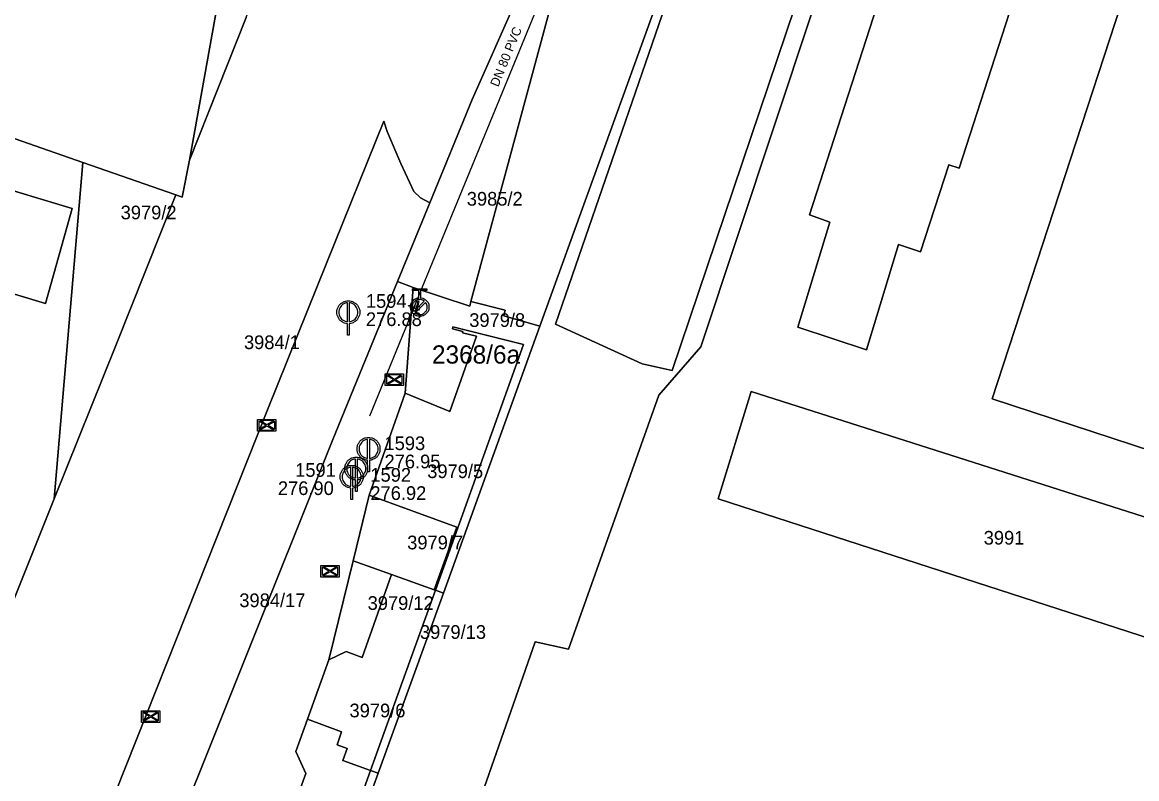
# Model space of a CAD drawing. Extents: x -570104 to -569328, y -1087857 to -1087418.
# Drawn here: x -569780.6 to -569658.3, y -1087753.5 to -1087670.5 of the extents above; entities that cross this region are included whole.
import ezdxf

# ---------------------------------------------------------------- set-up
doc = ezdxf.new("R2010")
doc.units = 0
for name, color, linetype in [('Adresní místo-text', 7, 'Continuous'), ('Armatura vodovodní', 7, 'Continuous'), ('Default', 7, 'Continuous'), ('Dešťová vpusť', 7, 'Continuous'), ('Hydrant', 7, 'Continuous'), ('Kanalizační šachta', 7, 'Continuous'), ('Parcela-polygon', 7, 'Continuous'), ('Parcela-text', 7, 'Continuous'), ('Popis šachty', 7, 'Continuous'), ('Přípojka vodovodní popis', 7, 'Continuous'), ('Vodovodní přípojka', 7, 'Continuous')]:
    doc.layers.add(name, color=color, linetype=linetype)

msp = doc.modelspace()

# ---------------------------------------------------------------- linework, layer by layer
at = {"layer": 'Armatura vodovodní'}
for points in [[(-569737.06, -1087701.1), (-569737.32, -1087702.32), (-569737.39, -1087702.3), (-569737.14, -1087701.08), (-569737.06, -1087701.1)], [(-569737.03, -1087702.12), (-569738.18, -1087701.65), (-569738.15, -1087701.57), (-569737, -1087702.05), (-569737.03, -1087702.12)]]:
    msp.add_lwpolyline(points, dxfattribs=at)
at = {"layer": 'Default'}
for points in [[(-569744.89, -1087703.59), (-569745.15, -1087703.57), (-569745.41, -1087703.42), (-569745.71, -1087703.26), (-569745.88, -1087702.96), (-569746.04, -1087702.66), (-569746.04, -1087702.34), (-569746.04, -1087702.01), (-569745.87, -1087701.71), (-569745.7, -1087701.41), (-569745.41, -1087701.25), (-569745.11, -1087701.09), (-569744.79, -1087701.09), (-569744.48, -1087701.09), (-569744.18, -1087701.25), (-569743.88, -1087701.41), (-569743.71, -1087701.71), (-569743.54, -1087702.01), (-569743.54, -1087702.34), (-569743.54, -1087702.66), (-569743.7, -1087702.96), (-569743.87, -1087703.26), (-569744.17, -1087703.42), (-569744.43, -1087703.57), (-569744.69, -1087703.59)], [(-569744.89, -1087701.3), (-569745.09, -1087701.32), (-569745.31, -1087701.43), (-569745.55, -1087701.57), (-569745.69, -1087701.82), (-569745.83, -1087702.07), (-569745.83, -1087702.34), (-569745.83, -1087702.61), (-569745.7, -1087702.86), (-569745.56, -1087703.1), (-569745.31, -1087703.24), (-569745.1, -1087703.36), (-569744.89, -1087703.38)], [(-569744.69, -1087703.38), (-569744.48, -1087703.36), (-569744.27, -1087703.24), (-569744.02, -1087703.1), (-569743.88, -1087702.86), (-569743.75, -1087702.61), (-569743.75, -1087702.34), (-569743.75, -1087702.07), (-569743.89, -1087701.82), (-569744.03, -1087701.57), (-569744.28, -1087701.43), (-569744.49, -1087701.32), (-569744.69, -1087701.3)], [(-569736.86, -1087700.76), (-569736.5, -1087700.79), (-569736.25, -1087701.05), (-569735.95, -1087701.34), (-569735.95, -1087701.76), (-569735.95, -1087702.17), (-569736.25, -1087702.47), (-569736.54, -1087702.76), (-569736.96, -1087702.76), (-569737.37, -1087702.76), (-569737.66, -1087702.47), (-569737.95, -1087702.17), (-569737.95, -1087701.76), (-569737.95, -1087701.34), (-569737.66, -1087701.05), (-569737.41, -1087700.79), (-569737.05, -1087700.76)], [(-569736.45, -1087701.12), (-569736.67, -1087700.94), (-569736.96, -1087700.94), (-569737.29, -1087700.94), (-569737.53, -1087701.18), (-569737.77, -1087701.42), (-569737.77, -1087701.76), (-569737.77, -1087702.05), (-569737.59, -1087702.26)], [(-569737.46, -1087702.4), (-569737.25, -1087702.57), (-569736.96, -1087702.57), (-569736.62, -1087702.57), (-569736.38, -1087702.33), (-569736.14, -1087702.09), (-569736.14, -1087701.76), (-569736.14, -1087701.47), (-569736.32, -1087701.25)], [(-569742.67, -1087718.58), (-569742.93, -1087718.56), (-569743.19, -1087718.41), (-569743.49, -1087718.25), (-569743.66, -1087717.95), (-569743.82, -1087717.65), (-569743.82, -1087717.33), (-569743.82, -1087717), (-569743.65, -1087716.7), (-569743.48, -1087716.4), (-569743.19, -1087716.24), (-569742.89, -1087716.08), (-569742.57, -1087716.08), (-569742.26, -1087716.08), (-569741.96, -1087716.24), (-569741.66, -1087716.4), (-569741.49, -1087716.7), (-569741.32, -1087717), (-569741.32, -1087717.33), (-569741.32, -1087717.65), (-569741.48, -1087717.95), (-569741.65, -1087718.25), (-569741.95, -1087718.41), (-569742.21, -1087718.56), (-569742.47, -1087718.58)], [(-569742.67, -1087716.29), (-569742.87, -1087716.31), (-569743.09, -1087716.42), (-569743.33, -1087716.56), (-569743.47, -1087716.81), (-569743.61, -1087717.06), (-569743.61, -1087717.33), (-569743.61, -1087717.6), (-569743.48, -1087717.85), (-569743.34, -1087718.09), (-569743.09, -1087718.23), (-569742.88, -1087718.35), (-569742.67, -1087718.37)], [(-569742.47, -1087718.37), (-569742.26, -1087718.35), (-569742.05, -1087718.23), (-569741.8, -1087718.09), (-569741.66, -1087717.85), (-569741.53, -1087717.6), (-569741.53, -1087717.33), (-569741.53, -1087717.06), (-569741.67, -1087716.81), (-569741.81, -1087716.56), (-569742.06, -1087716.42), (-569742.27, -1087716.31), (-569742.47, -1087716.29)], [(-569744.02, -1087720.74), (-569744.28, -1087720.72), (-569744.54, -1087720.57), (-569744.84, -1087720.41), (-569745.01, -1087720.11), (-569745.17, -1087719.81), (-569745.17, -1087719.49), (-569745.17, -1087719.16), (-569745, -1087718.86), (-569744.83, -1087718.56), (-569744.54, -1087718.4), (-569744.24, -1087718.24), (-569743.92, -1087718.24), (-569743.61, -1087718.24), (-569743.31, -1087718.4), (-569743.01, -1087718.56), (-569742.84, -1087718.86), (-569742.67, -1087719.16), (-569742.67, -1087719.49), (-569742.67, -1087719.81), (-569742.83, -1087720.11), (-569743, -1087720.41), (-569743.3, -1087720.57), (-569743.56, -1087720.72), (-569743.82, -1087720.74)], [(-569744.02, -1087718.45), (-569744.22, -1087718.47), (-569744.44, -1087718.58), (-569744.68, -1087718.72), (-569744.82, -1087718.97), (-569744.96, -1087719.22), (-569744.96, -1087719.49), (-569744.96, -1087719.76), (-569744.83, -1087720.01), (-569744.69, -1087720.25), (-569744.44, -1087720.39), (-569744.23, -1087720.51), (-569744.02, -1087720.53)], [(-569743.82, -1087720.53), (-569743.61, -1087720.51), (-569743.4, -1087720.39), (-569743.15, -1087720.25), (-569743.01, -1087720.01), (-569742.88, -1087719.76), (-569742.88, -1087719.49), (-569742.88, -1087719.22), (-569743.02, -1087718.97), (-569743.16, -1087718.72), (-569743.41, -1087718.58), (-569743.62, -1087718.47), (-569743.82, -1087718.45)], [(-569744.52, -1087721.64), (-569744.78, -1087721.62), (-569745.04, -1087721.47), (-569745.34, -1087721.31), (-569745.51, -1087721.01), (-569745.67, -1087720.71), (-569745.67, -1087720.39), (-569745.67, -1087720.06), (-569745.5, -1087719.76), (-569745.33, -1087719.46), (-569745.04, -1087719.3), (-569744.74, -1087719.14), (-569744.42, -1087719.14), (-569744.11, -1087719.14), (-569743.81, -1087719.3), (-569743.51, -1087719.46), (-569743.34, -1087719.76), (-569743.17, -1087720.06), (-569743.17, -1087720.39), (-569743.17, -1087720.71), (-569743.33, -1087721.01), (-569743.5, -1087721.31), (-569743.8, -1087721.47), (-569744.06, -1087721.62), (-569744.32, -1087721.64)], [(-569744.52, -1087719.35), (-569744.72, -1087719.37), (-569744.94, -1087719.48), (-569745.18, -1087719.62), (-569745.32, -1087719.87), (-569745.46, -1087720.12), (-569745.46, -1087720.39), (-569745.46, -1087720.66), (-569745.33, -1087720.91), (-569745.19, -1087721.15), (-569744.94, -1087721.29), (-569744.73, -1087721.41), (-569744.52, -1087721.43)], [(-569744.32, -1087721.43), (-569744.11, -1087721.41), (-569743.9, -1087721.29), (-569743.65, -1087721.15), (-569743.51, -1087720.91), (-569743.38, -1087720.66), (-569743.38, -1087720.39), (-569743.38, -1087720.12), (-569743.52, -1087719.87), (-569743.66, -1087719.62), (-569743.91, -1087719.48), (-569744.12, -1087719.37), (-569744.32, -1087719.35)]]:
    msp.add_open_spline(points, degree=3, dxfattribs=at)
at = {"layer": 'Dešťová vpusť'}
for points in [[(-569740.74, -1087710.38), (-569740.74, -1087709.1), (-569738.74, -1087709.1), (-569738.74, -1087710.38), (-569740.74, -1087710.38)], [(-569739.85, -1087709.73), (-569740.61, -1087709.28), (-569740.61, -1087710.19), (-569739.85, -1087709.73)], [(-569739.72, -1087709.81), (-569740.49, -1087710.26), (-569738.96, -1087710.26), (-569739.72, -1087709.81)], [(-569739.72, -1087709.66), (-569738.98, -1087709.22), (-569740.47, -1087709.22), (-569739.72, -1087709.66)], [(-569738.87, -1087710.17), (-569738.87, -1087709.3), (-569739.6, -1087709.73), (-569738.87, -1087710.17)], [(-569754.74, -1087715.39), (-569754.74, -1087714.11), (-569752.74, -1087714.11), (-569752.74, -1087715.39), (-569754.74, -1087715.39)], [(-569753.85, -1087714.74), (-569754.61, -1087714.29), (-569754.61, -1087715.2), (-569753.85, -1087714.74)], [(-569753.72, -1087714.82), (-569754.49, -1087715.27), (-569752.96, -1087715.27), (-569753.72, -1087714.82)], [(-569753.72, -1087714.67), (-569752.98, -1087714.23), (-569754.47, -1087714.23), (-569753.72, -1087714.67)], [(-569752.87, -1087715.18), (-569752.87, -1087714.31), (-569753.6, -1087714.74), (-569752.87, -1087715.18)], [(-569747.8, -1087731.39), (-569747.8, -1087730.11), (-569745.8, -1087730.11), (-569745.8, -1087731.39), (-569747.8, -1087731.39)], [(-569746.91, -1087730.74), (-569747.67, -1087730.29), (-569747.67, -1087731.2), (-569746.91, -1087730.74)], [(-569746.78, -1087730.82), (-569747.55, -1087731.27), (-569746.02, -1087731.27), (-569746.78, -1087730.82)], [(-569746.78, -1087730.67), (-569746.04, -1087730.23), (-569747.53, -1087730.23), (-569746.78, -1087730.67)], [(-569745.93, -1087731.18), (-569745.93, -1087730.31), (-569746.66, -1087730.74), (-569745.93, -1087731.18)], [(-569767.48, -1087747.33), (-569767.48, -1087746.05), (-569765.48, -1087746.05), (-569765.48, -1087747.33), (-569767.48, -1087747.33)], [(-569766.59, -1087746.68), (-569767.35, -1087746.23), (-569767.35, -1087747.14), (-569766.59, -1087746.68)], [(-569766.46, -1087746.61), (-569765.72, -1087746.17), (-569767.21, -1087746.17), (-569766.46, -1087746.61)], [(-569765.61, -1087747.12), (-569765.61, -1087746.25), (-569766.34, -1087746.68), (-569765.61, -1087747.12)], [(-569766.46, -1087746.76), (-569767.23, -1087747.21), (-569765.7, -1087747.21), (-569766.46, -1087746.76)]]:
    msp.add_lwpolyline(points, dxfattribs=at)
at = {"layer": 'Hydrant'}
for points in [[(-569737.05, -1087700.76), (-569737.05, -1087699.95), (-569737.74, -1087699.95), (-569737.74, -1087699.76), (-569736.17, -1087699.76), (-569736.17, -1087699.95), (-569736.86, -1087699.95), (-569736.86, -1087700.76)], [(-569737.59, -1087702.26), (-569736.45, -1087701.12)], [(-569736.32, -1087701.25), (-569737.46, -1087702.4)]]:
    msp.add_lwpolyline(points, dxfattribs=at)
at = {"layer": 'Kanalizační šachta'}
for points in [[(-569744.89, -1087703.38), (-569744.89, -1087701.3)], [(-569744.69, -1087701.3), (-569744.69, -1087703.38)], [(-569744.69, -1087703.59), (-569744.69, -1087704.84), (-569744.89, -1087704.84), (-569744.89, -1087703.59)], [(-569742.67, -1087718.37), (-569742.67, -1087716.29)], [(-569742.47, -1087716.29), (-569742.47, -1087718.37)], [(-569744.02, -1087720.53), (-569744.02, -1087718.45)], [(-569743.82, -1087718.45), (-569743.82, -1087720.53)], [(-569742.47, -1087718.58), (-569742.47, -1087719.83), (-569742.67, -1087719.83), (-569742.67, -1087718.58)], [(-569744.52, -1087721.43), (-569744.52, -1087719.35)], [(-569744.32, -1087719.35), (-569744.32, -1087721.43)], [(-569743.82, -1087720.74), (-569743.82, -1087721.99), (-569744.02, -1087721.99), (-569744.02, -1087720.74)], [(-569744.32, -1087721.64), (-569744.32, -1087722.89), (-569744.52, -1087722.89), (-569744.52, -1087721.64)]]:
    msp.add_lwpolyline(points, dxfattribs=at)
at = {"layer": 'Parcela-polygon'}
for points in [[(-569793.31, -1087679.13), (-569773.93, -1087685.9), (-569763.73, -1087689.47), (-569763.01, -1087689.72), (-569762.21, -1087685.64), (-569752, -1087628.8), (-569745.23, -1087597.37), (-569762.2, -1087592.33), (-569767.95, -1087620.6), (-569765.97, -1087621.01), (-569768.78, -1087634.92), (-569770.77, -1087634.51), (-569772.66, -1087643.77), (-569791.42, -1087639.95)], [(-569746.61, -1087802.34), (-569724.3, -1087738.5), (-569720.63, -1087739.3), (-569710.72, -1087711.45), (-569706.1, -1087706.13), (-569677.75, -1087620.8), (-569675.24, -1087615.77), (-569677.5, -1087614.66), (-569709.27, -1087708.71), (-569712.54, -1087708.01), (-569722.07, -1087703.64), (-569688.74, -1087606.97), (-569723.77, -1087703.85), (-569734.36, -1087733.15), (-569741.51, -1087752.92), (-569751.5, -1087780.56), (-569757.72, -1087797.76)], [(-569656.08, -1087623.85), (-569670.86, -1087616.21), (-569676.9, -1087612.89), (-569676.97, -1087613.11), (-569677.5, -1087614.66), (-569675.24, -1087615.77), (-569677.75, -1087620.8), (-569706.1, -1087706.13), (-569710.72, -1087711.45), (-569720.63, -1087739.3), (-569724.3, -1087738.5), (-569746.61, -1087802.34)], [(-569673.39, -1087629.36), (-569668.72, -1087630.86), (-569668.3, -1087629.52), (-569666.4, -1087630.12), (-569666.82, -1087631.48), (-569661.77, -1087633.12), (-569664.35, -1087641.09), (-569663.2, -1087641.46), (-569677.76, -1087686.51), (-569678.9, -1087686.15), (-569681.99, -1087695.71), (-569684.42, -1087694.89), (-569687.94, -1087706.45), (-569695.48, -1087703.96), (-569691.97, -1087692.47), (-569694.18, -1087691.63), (-569674, -1087629.15), (-569673.39, -1087629.36)], [(-569674.15, -1087711.83), (-569651.41, -1087642.32), (-569633.25, -1087648.27), (-569643.94, -1087679.59), (-569636.12, -1087682.33), (-569634.05, -1087683.06), (-569635, -1087686.54), (-569636.91, -1087686.03), (-569640.33, -1087695.74), (-569648.38, -1087693.02), (-569656.5, -1087717.61), (-569674.15, -1087711.83)], [(-569773.64, -1087763.31), (-569753.65, -1087713.04), (-569747.16, -1087696.87), (-569740.88, -1087681.36), (-569740.52, -1087682.49), (-569739.04, -1087686.03), (-569737.61, -1087689.09), (-569736.88, -1087689.77), (-569735.85, -1087690.34), (-569731.2, -1087679), (-569716.23, -1087645.29)], [(-569756, -1087670), (-569762.21, -1087685.64), (-569763.01, -1087689.72), (-569763.73, -1087689.47), (-569770.3, -1087706), (-569777.06, -1087722.81), (-569788.63, -1087751.58)], [(-569818.35, -1087689.28), (-569815.37, -1087679.15), (-569816.77, -1087678.74), (-569815.83, -1087675.53), (-569812.15, -1087676.61), (-569813.02, -1087679.56), (-569775.08, -1087690.97), (-569778.02, -1087701.37), (-569801.13, -1087694.44), (-569802.83, -1087700.11), (-569820.04, -1087695.04), (-569818.35, -1087689.28)], [(-569788.63, -1087751.58), (-569777.06, -1087722.81), (-569773.93, -1087685.9), (-569793.31, -1087679.13)], [(-569776.13, -1087790.17), (-569766.4, -1087766), (-569746.5, -1087716.3), (-569739.39, -1087698.97), (-569735.85, -1087690.34), (-569736.88, -1087689.77), (-569737.61, -1087689.09), (-569739.04, -1087686.03), (-569740.52, -1087682.49), (-569740.88, -1087681.36), (-569747.16, -1087696.87), (-569753.65, -1087713.04), (-569773.64, -1087763.31), (-569779.09, -1087777.66), (-569780.06, -1087788.55)], [(-569768.4, -1087793.36), (-569751.5, -1087780.56), (-569741.51, -1087752.92), (-569742.34, -1087752.62), (-569749.29, -1087772), (-569755.49, -1087769.51), (-569749.45, -1087752.96), (-569750.55, -1087750.53), (-569749.27, -1087746.98), (-569746.92, -1087740.49), (-569744.26, -1087729.61), (-569742.5, -1087722.41), (-569738.57, -1087711.21), (-569737.69, -1087699.63), (-569739.39, -1087698.97), (-569746.5, -1087716.3), (-569766.4, -1087766), (-569776.13, -1087790.17)], [(-569704.22, -1087722.8), (-569700.58, -1087711.04), (-569643.25, -1087729.31), (-569646.89, -1087741.06), (-569647.63, -1087741.14), (-569704.22, -1087722.8)]]:
    msp.add_lwpolyline(points, dxfattribs=at)
for points in [[(-569734.91, -1087612.82), (-569741.25, -1087598.55), (-569745.23, -1087597.37), (-569752, -1087628.8), (-569762.21, -1087685.64), (-569756, -1087670)], [(-569691.3, -1087606.5), (-569700.1, -1087611.8), (-569705, -1087620), (-569716.23, -1087645.29), (-569731.33, -1087701.17), (-569727.59, -1087702.09), (-569727.74, -1087702.73), (-569723.77, -1087703.85), (-569688.74, -1087606.97)], [(-569688.74, -1087606.97), (-569722.07, -1087703.64), (-569712.54, -1087708.01), (-569709.27, -1087708.71), (-569677.5, -1087614.66), (-569676.97, -1087613.11), (-569676.9, -1087612.89), (-569677.4, -1087612.64)], [(-569673.39, -1087629.36), (-569674, -1087629.15), (-569694.18, -1087691.63), (-569691.97, -1087692.47), (-569695.48, -1087703.96), (-569687.94, -1087706.45), (-569684.42, -1087694.89), (-569681.99, -1087695.71), (-569678.9, -1087686.15), (-569677.76, -1087686.51), (-569663.2, -1087641.46), (-569664.35, -1087641.09), (-569661.77, -1087633.12), (-569666.82, -1087631.48), (-569666.4, -1087630.12), (-569668.3, -1087629.52), (-569668.72, -1087630.86)], [(-569674.15, -1087711.83), (-569656.5, -1087717.61), (-569648.38, -1087693.02), (-569640.33, -1087695.74), (-569636.91, -1087686.03), (-569635, -1087686.54), (-569634.05, -1087683.06), (-569636.12, -1087682.33), (-569643.94, -1087679.59), (-569633.25, -1087648.27), (-569651.41, -1087642.32)], [(-569735.85, -1087690.34), (-569739.39, -1087698.97), (-569737.69, -1087699.63), (-569731.47, -1087701.68), (-569731.33, -1087701.17), (-569716.23, -1087645.29), (-569731.2, -1087679)], [(-569816.77, -1087678.74), (-569815.37, -1087679.15), (-569818.35, -1087689.28), (-569820.04, -1087695.04), (-569802.83, -1087700.11), (-569801.13, -1087694.44), (-569778.02, -1087701.37), (-569775.08, -1087690.97), (-569813.02, -1087679.56), (-569812.15, -1087676.61), (-569815.83, -1087675.53)], [(-569777.06, -1087722.81), (-569770.3, -1087706), (-569763.73, -1087689.47), (-569773.93, -1087685.9)], [(-569733.31, -1087703.93), (-569725.57, -1087705.87), (-569735.24, -1087732.83), (-569734.36, -1087733.15), (-569723.77, -1087703.85), (-569727.74, -1087702.73), (-569727.59, -1087702.09), (-569731.33, -1087701.17), (-569731.47, -1087701.68), (-569737.69, -1087699.63), (-569738.57, -1087711.21), (-569733.66, -1087713.24), (-569730.71, -1087704.97), (-569732.26, -1087704.59), (-569732.22, -1087704.45), (-569733.37, -1087704.17)], [(-569733.37, -1087704.17), (-569732.22, -1087704.45), (-569732.26, -1087704.59), (-569730.71, -1087704.97), (-569733.66, -1087713.24), (-569738.57, -1087711.21), (-569742.5, -1087722.41), (-569732.9, -1087725.9), (-569735.36, -1087732.79), (-569735.24, -1087732.83), (-569725.57, -1087705.87), (-569733.31, -1087703.93)], [(-569704.22, -1087722.8), (-569647.63, -1087741.14), (-569646.89, -1087741.06), (-569643.25, -1087729.31), (-569700.58, -1087711.04)], [(-569732.9, -1087725.9), (-569742.5, -1087722.41), (-569744.26, -1087729.61), (-569740.04, -1087731.12), (-569735.36, -1087732.79)], [(-569740.04, -1087731.12), (-569744.26, -1087729.61), (-569746.92, -1087740.49), (-569745.01, -1087739.57), (-569743.28, -1087740.2)], [(-569742.34, -1087752.62), (-569738.5, -1087741.93), (-569735.24, -1087732.83), (-569735.36, -1087732.79), (-569740.04, -1087731.12), (-569743.28, -1087740.2), (-569745.01, -1087739.57), (-569746.92, -1087740.49), (-569749.27, -1087746.98), (-569745.52, -1087748.39), (-569746.03, -1087749.8), (-569744.9, -1087750.21), (-569745.38, -1087751.52)], [(-569741.51, -1087752.92), (-569734.36, -1087733.15), (-569735.24, -1087732.83), (-569738.5, -1087741.93), (-569742.34, -1087752.62)], [(-569749.27, -1087746.98), (-569750.55, -1087750.53), (-569749.45, -1087752.96), (-569755.49, -1087769.51), (-569749.29, -1087772), (-569742.34, -1087752.62), (-569745.38, -1087751.52), (-569744.9, -1087750.21), (-569746.03, -1087749.8), (-569745.52, -1087748.39)]]:
    msp.add_lwpolyline(points, close=True, dxfattribs=at)
at = {"layer": 'Vodovodní přípojka'}
for points in [[(-569704.52, -1087621.35), (-569704.61, -1087621.49), (-569737.51, -1087701.64), (-569737.59, -1087701.85), (-569742.47, -1087713.74)], [(-569737.51, -1087701.64), (-569737.5, -1087701.64), (-569737.23, -1087701.7), (-569736.95, -1087701.76)]]:
    msp.add_lwpolyline(points, dxfattribs=at)

# ---------------------------------------------------------------- texts
at = {"layer": 'Adresní místo-text'}
msp.add_text('2368/6a', height=2, dxfattribs=at).set_placement((-569735.61, -1087707.97))
at = {"layer": 'Parcela-text'}
for s, p in [('3985/2', (-569731.79, -1087690.64)), ('3979/2', (-569769.77, -1087692.14)), ('3979/8', (-569731.52, -1087703.95)), ('3984/1', (-569756.24, -1087706.38)), ('3979/5', (-569736.13, -1087720.53)), ('3979/7', (-569738.33, -1087728.35)), ('3991', (-569675.07, -1087727.83)), ('3984/17', (-569756.75, -1087734.69)), ('3979/12', (-569742.67, -1087734.99)), ('3979/13', (-569736.93, -1087738.17)), ('3979/6', (-569744.66, -1087746.78))]:
    msp.add_text(s, height=1.5, dxfattribs=at).set_placement(p)
at = {"layer": 'Popis šachty'}
for s, p in [('1594', (-569742.86, -1087701.85)), ('276.88', (-569742.86, -1087703.85)), ('1593', (-569740.82, -1087717.46)), ('276.95', (-569740.82, -1087719.46)), ('1591', (-569750.62, -1087720.39)), ('1592', (-569742.37, -1087720.93)), ('276.90', (-569752.52, -1087722.39)), ('276.92', (-569742.37, -1087722.93))]:
    msp.add_text(s, height=1.5, dxfattribs=at).set_placement(p)
at = {"layer": 'Přípojka vodovodní popis'}
msp.add_text('DN 80 PVC', height=1, rotation=67.7547, dxfattribs=at).set_placement((-569728.34, -1087677.68))

doc.saveas('drawing.dxf')
